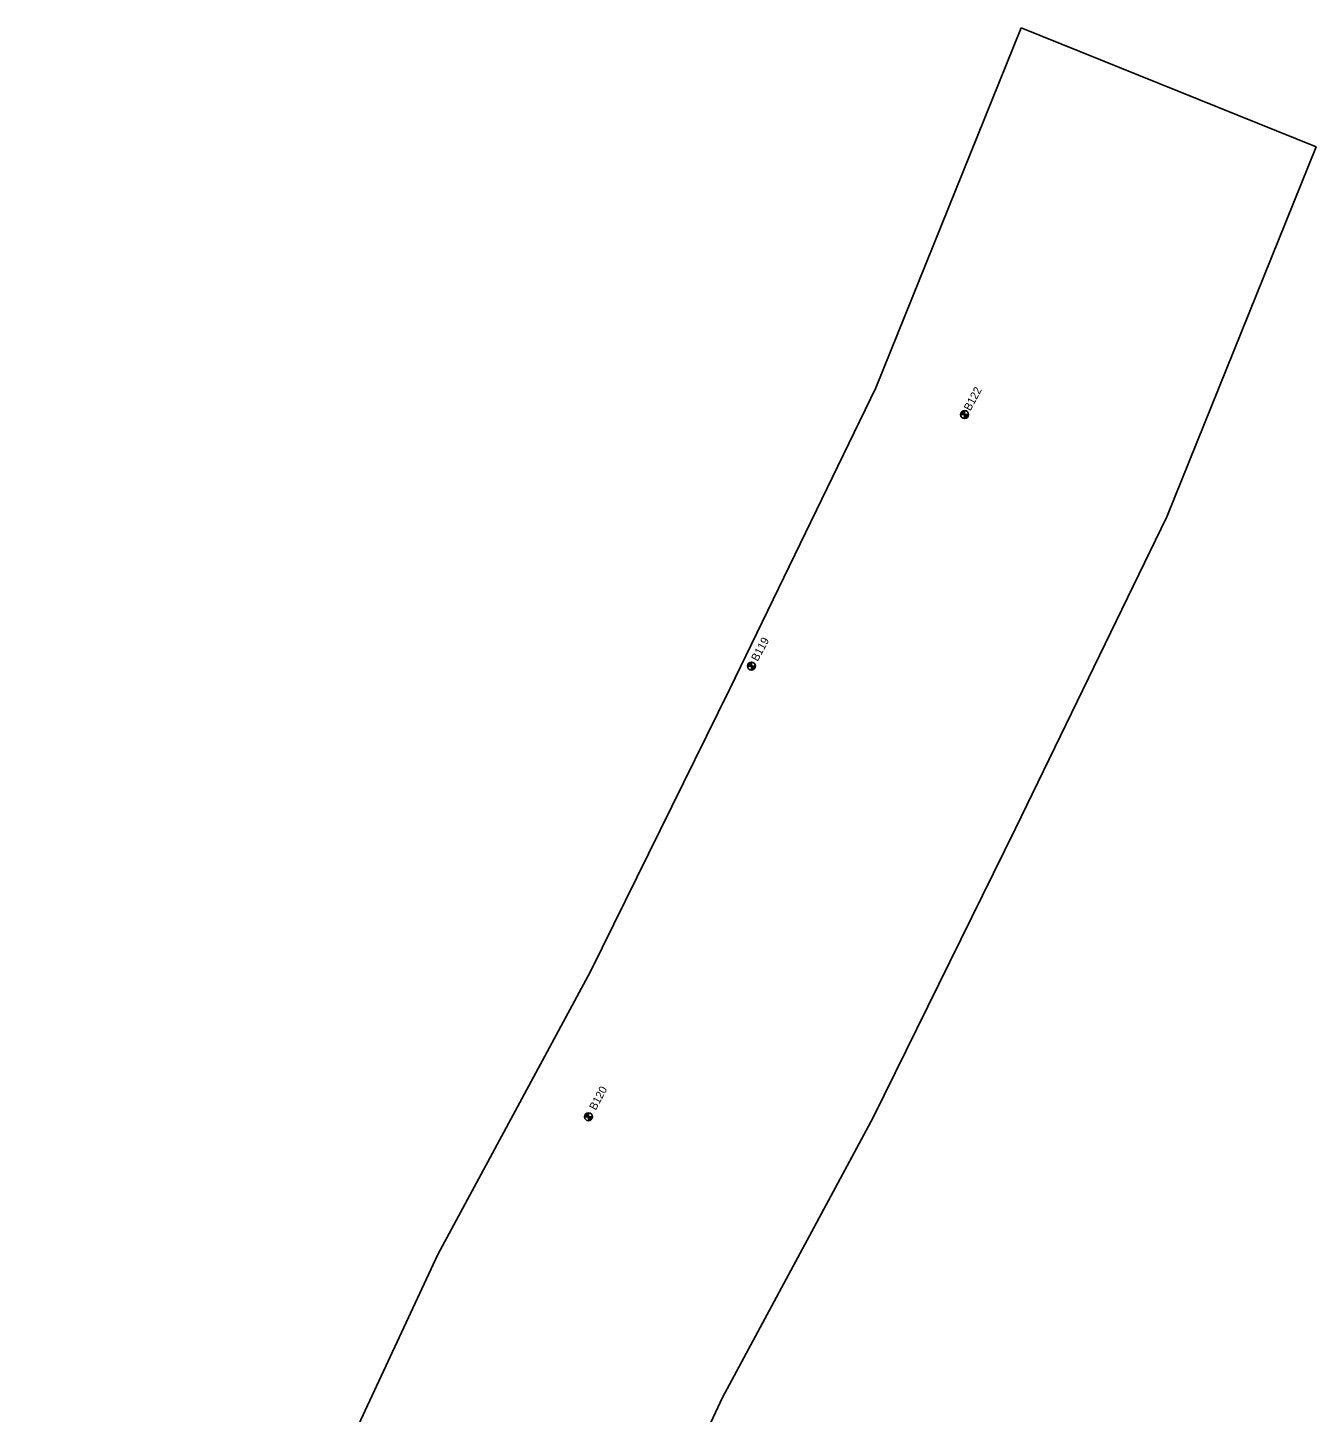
# Model space of a CAD drawing. Extents: x 327762 to 372792, y 127949 to 259367.
# Drawn here: x 355040 to 356660, y 193918 to 195659 of the extents above; entities that cross this region are included whole.
import ezdxf

# ---------------------------------------------------------------- set-up
doc = ezdxf.new("R2010")
doc.units = 0
for name, color, linetype in [('E_SOIL_BORE1 [KAPUR_CADDS_LEVELS]', 7, 'Continuous'), ('E_SOIL_BORE2 [KAPUR_CADDS_LEVELS]', 7, 'Continuous'), ('P_MARK', 7, 'Continuous'), ('P_TC', 7, 'Continuous')]:
    doc.layers.add(name, color=color, linetype=linetype)

msp = doc.modelspace()

# ---------------------------------------------------------------- linework, layer by layer
at = {"layer": 'P_MARK'}
for p, q in [((356213, 195172.4), (356223, 195172.4)), ((356218, 195177.4), (356218, 195167.4)), ((355950.1, 194861.3), (355950.1, 194851.3)), ((355945.1, 194856.3), (355955.1, 194856.3)), ((355740.3, 194289.7), (355750.3, 194289.7)), ((355745.3, 194294.7), (355745.3, 194284.7))]:
    msp.add_line(p, q, dxfattribs=at)
for centre in [(356218, 195172.4), (355950.1, 194856.3), (355745.3, 194289.7)]:
    msp.add_circle(centre, 5, dxfattribs=at)
for centre, radius, start, end in [((356218, 195172.4), 4.5, 89.9869, 179.9869), ((356218, 195172.4), 4, 89.9869, 179.9869), ((356218, 195172.4), 3.5, 89.9869, 179.9869), ((356218, 195172.4), 3, 89.9869, 179.9869), ((356218, 195172.4), 2.5, 89.9869, 179.9869), ((356218, 195172.4), 2, 89.9869, 179.9869), ((356218, 195172.4), 1.5, 89.9869, 179.9869), ((356218, 195172.4), 1, 89.9869, 179.9869), ((356218, 195172.4), 0.5, 89.9869, 179.9869), ((356218, 195172.4), 4.5, 269.9869, 359.9869), ((356218, 195172.4), 4, 269.9869, 359.9869), ((356218, 195172.4), 3.5, 269.9869, 359.9869), ((356218, 195172.4), 3, 269.9869, 359.9869), ((356218, 195172.4), 2.5, 269.9869, 359.9869), ((356218, 195172.4), 2, 269.9869, 359.9869), ((356218, 195172.4), 1.5, 269.9869, 359.9869), ((356218, 195172.4), 1, 269.9869, 359.9869), ((356218, 195172.4), 0.5, 269.9869, 359.9869), ((355950.1, 194856.3), 4.5, 89.9869, 179.9869), ((355950.1, 194856.3), 4, 89.9869, 179.9869), ((355950.1, 194856.3), 3.5, 89.9869, 179.9869), ((355950.1, 194856.3), 3, 89.9869, 179.9869), ((355950.1, 194856.3), 2.5, 89.9869, 179.9869), ((355950.1, 194856.3), 2, 89.9869, 179.9869), ((355950.1, 194856.3), 1.5, 89.9869, 179.9869), ((355950.1, 194856.3), 1, 89.9869, 179.9869), ((355950.1, 194856.3), 0.5, 89.9869, 179.9869), ((355950.1, 194856.3), 4.5, 269.9869, 359.9869), ((355950.1, 194856.3), 4, 269.9869, 359.9869), ((355950.1, 194856.3), 3.5, 269.9869, 359.9869), ((355950.1, 194856.3), 3, 269.9869, 359.9869), ((355950.1, 194856.3), 2.5, 269.9869, 359.9869), ((355950.1, 194856.3), 2, 269.9869, 359.9869), ((355950.1, 194856.3), 1.5, 269.9869, 359.9869), ((355950.1, 194856.3), 1, 269.9869, 359.9869), ((355950.1, 194856.3), 0.5, 269.9869, 359.9869), ((355745.3, 194289.7), 4.5, 89.9869, 179.9869), ((355745.3, 194289.7), 4, 89.9869, 179.9869), ((355745.3, 194289.7), 3.5, 89.9869, 179.9869), ((355745.3, 194289.7), 3, 89.9869, 179.9869), ((355745.3, 194289.7), 2.5, 89.9869, 179.9869), ((355745.3, 194289.7), 2, 89.9869, 179.9869), ((355745.3, 194289.7), 1.5, 89.9869, 179.9869), ((355745.3, 194289.7), 1, 89.9869, 179.9869), ((355745.3, 194289.7), 0.5, 89.9869, 179.9869), ((355745.3, 194289.7), 4.5, 269.9869, 359.9869), ((355745.3, 194289.7), 4, 269.9869, 359.9869), ((355745.3, 194289.7), 3.5, 269.9869, 359.9869), ((355745.3, 194289.7), 3, 269.9869, 359.9869), ((355745.3, 194289.7), 2.5, 269.9869, 359.9869), ((355745.3, 194289.7), 2, 269.9869, 359.9869), ((355745.3, 194289.7), 1.5, 269.9869, 359.9869), ((355745.3, 194289.7), 1, 269.9869, 359.9869), ((355745.3, 194289.7), 0.5, 269.9869, 359.9869)]:
    msp.add_arc(centre, radius, start, end, dxfattribs=at)
at = {"layer": 'P_TC'}
msp.add_line((356289.3, 195658.8), (356660.1, 195508.9), dxfattribs=at)
for points in [[(355283.6, 189224), (355274.3, 189348.2), (355249.7, 189692.4), (355212.6, 190196.5), (355174, 190629), (355143, 191045.2), (355065.1, 191886.3), (355040.4, 192233.4), (355074.6, 192700.4), (355130.4, 193038.8), (355243.3, 193407.8), (355370.8, 193719.1), (355556, 194116.5), (355747.6, 194472.4), (355922.8, 194827.6), (356106.3, 195206.2), (356289.3, 195658.8)], [(356660.1, 195508.9), (356472.1, 195043.8), (356282.2, 194652), (356103.2, 194289), (355913.6, 193937), (355737.4, 193558.7), (355620.5, 193273.2), (355520.7, 192947.3), (355472.2, 192653.1), (355441.4, 192233), (355463.8, 191918.9), (355541.6, 191078.5), (355572.6, 190661.6), (355611.3, 190229), (355648.6, 189721.3), (355673.2, 189377.4), (355691.8, 189129.9)]]:
    msp.add_lwpolyline(points, dxfattribs=at)

# ---------------------------------------------------------------- texts
at = {"layer": 'E_SOIL_BORE1 [KAPUR_CADDS_LEVELS]'}
msp.add_text('B122', height=10, rotation=61.5935, dxfattribs=at).set_placement((356225.2, 195176.3))
at = {"layer": 'E_SOIL_BORE2 [KAPUR_CADDS_LEVELS]'}
for s, p in [('B119', (355957.9, 194861.5)), ('B120', (355754.3, 194297.2))]:
    msp.add_text(s, height=10, rotation=61.5935, dxfattribs=at).set_placement(p)

doc.saveas('drawing.dxf')
